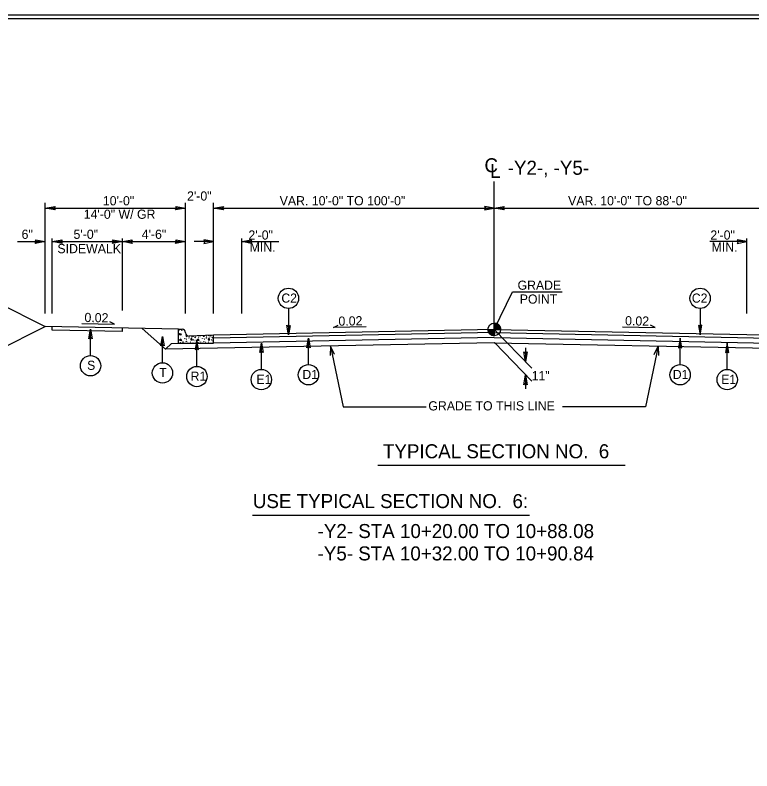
# Model space of a CAD drawing. Extents: x 1901670 to 1902225, y 193498 to 194278.
# Drawn here: x 1902005.8 to 1902058.3, y 193881.9 to 193935.8 of the extents above; entities that cross this region are included whole.
import ezdxf

# ---------------------------------------------------------------- set-up
doc = ezdxf.new("R2010")
doc.units = 0
for name, color, linetype in [('Old_Level_1', 7, 'Continuous'), ('Old_Level_11', 7, 'Continuous'), ('Old_Level_2', 7, 'Continuous'), ('Old_Level_20', 7, 'Continuous'), ('Prop Dimension', 7, 'Continuous'), ('Sheet Border Standard 30in CELL', 7, 'Continuous'), ('Sheet Plot Border Inside CELL', 7, 'Continuous'), ('Typical Curb CELL', 7, 'Continuous'), ('Typical Pavement Slope CELL', 7, 'Continuous'), ('Typical Terminator CELL', 7, 'Continuous'), ('Typical Text Grade Point CELL', 7, 'Continuous')]:
    doc.layers.add(name, color=color, linetype=linetype)

# ---------------------------------------------------------------- blocks, each defined once
blk = doc.blocks.new('TERMINATOR')
at = {"layer": 'Typical Terminator CELL'}
blk.add_lwpolyline([(-0.469, 0.081), (0, 0), (-0.471, -0.083), (-0.411, 0)], close=True, dxfattribs=at)

msp = doc.modelspace()

# ---------------------------------------------------------------- linework, layer by layer
at = {"layer": 'Old_Level_1'}
for p, q in [((1902039.897, 193913.36), (1902039.897, 193923.919)), ((1902010.511, 193913.786), (1902012.826, 193913.738)), ((1902012.826, 193913.738), (1902012.493, 193913.905)), ((1902039.897, 193913.36), (1902039.897, 193913.81)), ((1902014.816, 193913.429), (1902016.474, 193911.944)), ((1902039.897, 193913.36), (1902019.897, 193912.96)), ((1902028.443, 193913.503), (1902028.776, 193913.67)), ((1902030.758, 193913.551), (1902028.443, 193913.503)), ((1902039.447, 193913.36), (1902039.897, 193913.36)), ((1902039.896, 193912.91), (1902039.897, 193913.36)), ((1902039.897, 193913.36), (1902039.896, 193912.91)), ((1902039.897, 193913.36), (1902042.569, 193910.6)), ((1902040.347, 193913.36), (1902039.897, 193913.36)), ((1902039.897, 193913.36), (1902057.897, 193913)), ((1902049.035, 193913.551), (1902051.35, 193913.503)), ((1902051.35, 193913.503), (1902051.017, 193913.67)), ((1902039.897, 193913.142), (1902019.897, 193912.742)), ((1902039.897, 193912.777), (1902019.897, 193912.377)), ((1902039.897, 193913.142), (1902059.897, 193912.742)), ((1902039.897, 193912.777), (1902059.897, 193912.377)), ((1902057.897, 193913), (1902059.897, 193912.96)), ((1902039.897, 193912.413), (1902016.474, 193911.944)), ((1902016.897, 193912.367), (1902016.474, 193911.944)), ((1902016.897, 193912.367), (1902017.397, 193912.377)), ((1902039.897, 193912.413), (1902063.319, 193911.944)), ((1902039.899, 193912.426), (1902042.569, 193909.667)), ((1902042.123, 193912.06), (1902042.123, 193911.06)), ((1902042.125, 193910.125), (1902042.125, 193909.125))]:
    msp.add_line(p, q, dxfattribs=at)
for points in [[(1902039.901, 193913.81), (1902039.901, 193913.81), (1902039.901, 193913.36)], [(1902039.91, 193913.81), (1902039.91, 193913.36)], [(1902039.919, 193913.809), (1902039.919, 193913.36)], [(1902039.928, 193913.809), (1902039.928, 193913.36)], [(1902039.937, 193913.808), (1902039.937, 193913.36)], [(1902039.946, 193913.807), (1902039.946, 193913.36)], [(1902039.955, 193913.806), (1902039.955, 193913.36)], [(1902039.964, 193913.805), (1902039.964, 193913.36)], [(1902039.973, 193913.804), (1902039.973, 193913.36)], [(1902039.982, 193913.802), (1902039.982, 193913.36)], [(1902039.991, 193913.8), (1902039.991, 193913.36)], [(1902040, 193913.798), (1902040, 193913.36)], [(1902040.009, 193913.796), (1902040.009, 193913.36)], [(1902040.018, 193913.793), (1902040.018, 193913.36)], [(1902040.027, 193913.791), (1902040.027, 193913.36)], [(1902040.036, 193913.788), (1902040.036, 193913.36)], [(1902040.045, 193913.785), (1902040.045, 193913.36)], [(1902040.054, 193913.782), (1902040.054, 193913.36)], [(1902040.063, 193913.778), (1902040.063, 193913.36)], [(1902040.072, 193913.774), (1902040.072, 193913.36)], [(1902040.081, 193913.77), (1902040.081, 193913.36)], [(1902040.09, 193913.766), (1902040.09, 193913.36)], [(1902040.099, 193913.762), (1902040.099, 193913.36)], [(1902040.108, 193913.757), (1902040.108, 193913.36)], [(1902040.117, 193913.752), (1902040.117, 193913.36)], [(1902040.126, 193913.747), (1902040.126, 193913.36)], [(1902039.449, 193913.36), (1902039.449, 193913.311)], [(1902039.458, 193913.36), (1902039.458, 193913.258)], [(1902039.467, 193913.36), (1902039.467, 193913.226)], [(1902039.476, 193913.36), (1902039.476, 193913.199)], [(1902039.485, 193913.36), (1902039.485, 193913.178)], [(1902039.494, 193913.36), (1902039.494, 193913.159)], [(1902039.503, 193913.36), (1902039.503, 193913.142)], [(1902039.512, 193913.36), (1902039.512, 193913.126)], [(1902039.521, 193913.36), (1902039.521, 193913.112)], [(1902039.53, 193913.36), (1902039.53, 193913.099)], [(1902039.539, 193913.36), (1902039.539, 193913.087)], [(1902039.548, 193913.36), (1902039.548, 193913.076)], [(1902039.557, 193913.36), (1902039.557, 193913.065)], [(1902039.566, 193913.36), (1902039.566, 193913.055)], [(1902039.575, 193913.36), (1902039.575, 193913.045)], [(1902039.584, 193913.36), (1902039.584, 193913.036)], [(1902039.593, 193913.36), (1902039.593, 193913.028)], [(1902039.602, 193913.36), (1902039.602, 193913.02)], [(1902039.611, 193913.36), (1902039.611, 193913.012)], [(1902039.62, 193913.36), (1902039.62, 193913.005)], [(1902039.629, 193913.36), (1902039.629, 193912.998)], [(1902039.638, 193913.36), (1902039.638, 193912.992)], [(1902039.647, 193913.36), (1902039.647, 193912.986)], [(1902039.656, 193913.36), (1902039.656, 193912.98)], [(1902039.665, 193913.36), (1902039.665, 193912.974)], [(1902039.674, 193913.36), (1902039.674, 193912.969)], [(1902039.683, 193913.36), (1902039.683, 193912.964)], [(1902039.692, 193913.36), (1902039.692, 193912.959)], [(1902039.701, 193913.36), (1902039.701, 193912.955)], [(1902039.71, 193913.36), (1902039.71, 193912.951)], [(1902039.719, 193913.36), (1902039.719, 193912.947)], [(1902039.728, 193913.36), (1902039.728, 193912.943)], [(1902039.737, 193913.36), (1902039.737, 193912.939)], [(1902039.746, 193913.36), (1902039.746, 193912.936)], [(1902039.755, 193913.36), (1902039.755, 193912.933)], [(1902039.764, 193913.36), (1902039.764, 193912.93)], [(1902039.773, 193913.36), (1902039.773, 193912.928)], [(1902039.782, 193913.36), (1902039.782, 193912.925)], [(1902039.791, 193913.36), (1902039.791, 193912.923)], [(1902039.8, 193913.36), (1902039.8, 193912.921)], [(1902039.809, 193913.36), (1902039.809, 193912.919)], [(1902039.818, 193913.36), (1902039.818, 193912.917)], [(1902039.827, 193913.36), (1902039.827, 193912.916)], [(1902039.836, 193913.36), (1902039.836, 193912.914)], [(1902039.845, 193913.36), (1902039.845, 193912.913)], [(1902039.854, 193913.36), (1902039.854, 193912.912)], [(1902039.863, 193913.36), (1902039.863, 193912.911)], [(1902039.872, 193913.36), (1902039.872, 193912.911)], [(1902039.881, 193913.36), (1902039.881, 193912.91)], [(1902039.89, 193913.36), (1902039.89, 193912.91), (1902039.89, 193912.91)], [(1902040.135, 193913.742), (1902040.135, 193913.36)], [(1902040.144, 193913.736), (1902040.144, 193913.36)], [(1902040.153, 193913.73), (1902040.153, 193913.36)], [(1902040.162, 193913.723), (1902040.162, 193913.36)], [(1902040.171, 193913.717), (1902040.171, 193913.36)], [(1902040.18, 193913.71), (1902040.18, 193913.36)], [(1902040.189, 193913.702), (1902040.189, 193913.36)], [(1902040.198, 193913.694), (1902040.198, 193913.36)], [(1902040.207, 193913.686), (1902040.207, 193913.36)], [(1902040.216, 193913.677), (1902040.216, 193913.36)], [(1902040.225, 193913.668), (1902040.225, 193913.36)], [(1902040.234, 193913.658), (1902040.234, 193913.36)], [(1902040.243, 193913.647), (1902040.243, 193913.36)], [(1902040.252, 193913.636), (1902040.252, 193913.36)], [(1902040.261, 193913.624), (1902040.261, 193913.36)], [(1902040.27, 193913.611), (1902040.27, 193913.36)], [(1902040.279, 193913.597), (1902040.279, 193913.36)], [(1902040.288, 193913.582), (1902040.288, 193913.36)], [(1902040.297, 193913.566), (1902040.297, 193913.36)], [(1902040.306, 193913.547), (1902040.306, 193913.36)], [(1902040.315, 193913.526), (1902040.315, 193913.36)], [(1902040.324, 193913.501), (1902040.324, 193913.36)], [(1902040.333, 193913.47), (1902040.333, 193913.36)], [(1902040.342, 193913.424), (1902040.342, 193913.36)], [(1902028.512, 193911.57), (1902028.219, 193912.179), (1902028.191, 193911.504)], [(1902028.219, 193912.179), (1902029.128, 193907.833)], [(1902051.575, 193912.179), (1902050.665, 193907.833)], [(1902051.281, 193911.57), (1902051.575, 193912.179), (1902051.602, 193911.504)], [(1902029.128, 193907.833), (1902035.043, 193907.833)], [(1902050.665, 193907.833), (1902044.75, 193907.833)]]:
    msp.add_lwpolyline(points, dxfattribs=at)
msp.add_circle((1902039.896, 193913.36), 0.45, dxfattribs=at)
for start, end in [(359.9905, 89.9905), (179.9905, 269.9905)]:
    msp.add_arc((1902039.896, 193913.36), 0.45, start, end, dxfattribs=at)
at = {"layer": 'Old_Level_11'}
for p, q in [((1902025.231, 193914.854), (1902025.231, 193912.98)), ((1902054.562, 193914.854), (1902054.562, 193912.98)), ((1902011.127, 193911.5), (1902011.127, 193913.374)), ((1902016.251, 193910.984), (1902016.251, 193912.859)), ((1902026.656, 193910.858), (1902026.656, 193912.732)), ((1902053.138, 193910.858), (1902053.138, 193912.732)), ((1902018.705, 193910.731), (1902018.705, 193912.605)), ((1902023.297, 193910.509), (1902023.297, 193912.384)), ((1902056.497, 193910.509), (1902056.497, 193912.384)), ((1902031.604, 193903.683), (1902048.23, 193903.683)), ((1902032.604, 193903.683), (1902049.23, 193903.683)), ((1902022.666, 193900.132), (1902042.41, 193900.132))]:
    msp.add_line(p, q, dxfattribs=at)
for points in [[(1902011.012, 193912.703), (1902011.127, 193913.374), (1902011.247, 193912.699), (1902011.127, 193912.785)], [(1902025.347, 193913.651), (1902025.231, 193912.98), (1902025.112, 193913.655), (1902025.231, 193913.569)], [(1902054.447, 193913.651), (1902054.562, 193912.98), (1902054.682, 193913.655), (1902054.562, 193913.569)], [(1902016.135, 193912.187), (1902016.251, 193912.859), (1902016.37, 193912.183), (1902016.251, 193912.269)], [(1902026.54, 193912.061), (1902026.656, 193912.732), (1902026.775, 193912.057), (1902026.656, 193912.143)], [(1902053.253, 193912.061), (1902053.138, 193912.732), (1902053.018, 193912.057), (1902053.138, 193912.143)], [(1902018.821, 193911.934), (1902018.705, 193912.605), (1902018.586, 193911.93), (1902018.705, 193912.016)], [(1902023.181, 193911.712), (1902023.297, 193912.384), (1902023.416, 193911.708), (1902023.297, 193911.794)], [(1902056.612, 193911.712), (1902056.497, 193912.384), (1902056.377, 193911.708), (1902056.497, 193911.794)]]:
    msp.add_lwpolyline(points, close=True, dxfattribs=at)
for centre in [(1902025.231, 193915.579), (1902054.562, 193915.579), (1902011.127, 193910.775), (1902016.251, 193910.259), (1902018.705, 193910.006), (1902026.656, 193910.133), (1902053.137, 193910.133), (1902023.297, 193909.784), (1902056.497, 193909.784)]:
    msp.add_circle(centre, 0.725, dxfattribs=at)
at = {"layer": 'Prop Dimension'}
for p, q in [((1902007.897, 193914.498), (1902007.897, 193922.38)), ((1902017.897, 193914.498), (1902017.897, 193922.38)), ((1902019.897, 193914.498), (1902019.897, 193922.38)), ((1902007.897, 193922.01), (1902017.897, 193922.01)), ((1902019.897, 193922.01), (1902039.897, 193922.01)), ((1902039.897, 193922.01), (1902059.897, 193922.01)), ((1902008.397, 193914.498), (1902008.397, 193919.848)), ((1902013.397, 193914.719), (1902013.397, 193919.848)), ((1902021.897, 193914.498), (1902021.897, 193919.848)), ((1902057.897, 193914.498), (1902057.897, 193919.848)), ((1902005.931, 193919.621), (1902007.897, 193919.621)), ((1902008.397, 193919.621), (1902013.397, 193919.621)), ((1902013.397, 193919.621), (1902017.897, 193919.621)), ((1902019.897, 193919.621), (1902018.513, 193919.621)), ((1902021.897, 193919.621), (1902024.542, 193919.621)), ((1902057.897, 193919.621), (1902055.251, 193919.621))]:
    msp.add_line(p, q, dxfattribs=at)
at = {"layer": 'Sheet Border Standard 30in CELL'}
msp.add_lwpolyline([(1902132.544, 193935.514), (1901982.544, 193935.514), (1901982.544, 193830.514), (1902132.544, 193830.514)], close=True, dxfattribs=at)
at = {"layer": 'Sheet Plot Border Inside CELL'}
msp.add_lwpolyline([(1902133.794, 193935.769), (1901967.144, 193935.769), (1901967.144, 193830.259), (1902133.794, 193830.259)], close=True, dxfattribs=at)
at = {"layer": 'Typical Curb CELL'}
for p, q in [((1902017.397, 193912.377), (1902017.397, 193913.377)), ((1902017.397, 193913.377), (1902017.657, 193913.377)), ((1902017.433, 193912.999), (1902017.588, 193913.044)), ((1902017.571, 193912.953), (1902017.433, 193912.999)), ((1902017.559, 193912.68), (1902017.456, 193912.605)), ((1902017.622, 193912.566), (1902017.559, 193912.68)), ((1902017.588, 193913.044), (1902017.571, 193912.953)), ((1902017.897, 193913.127), (1902017.897, 193913.137)), ((1902019.897, 193912.96), (1902018.146, 193912.887)), ((1902018.301, 193912.736), (1902018.267, 193912.623)), ((1902018.386, 193912.617), (1902018.301, 193912.736)), ((1902018.808, 193912.68), (1902018.705, 193912.605)), ((1902018.871, 193912.566), (1902018.808, 193912.68)), ((1902019.55, 193912.736), (1902019.515, 193912.623)), ((1902019.636, 193912.617), (1902019.55, 193912.736)), ((1902019.897, 193912.377), (1902019.897, 193912.96)), ((1902017.397, 193912.377), (1902019.897, 193912.377)), ((1902017.456, 193912.605), (1902017.622, 193912.566)), ((1902018.267, 193912.623), (1902018.386, 193912.617)), ((1902018.705, 193912.605), (1902018.871, 193912.566)), ((1902019.515, 193912.623), (1902019.636, 193912.617))]:
    msp.add_line(p, q, dxfattribs=at)
for centre in [(1902017.41, 193913.267), (1902017.627, 193913.301), (1902017.462, 193913.084), (1902017.559, 193912.811), (1902017.679, 193912.862), (1902017.856, 193912.697), (1902017.936, 193912.89), (1902017.953, 193912.84), (1902017.981, 193912.668), (1902018.13, 193912.754), (1902018.158, 193912.856), (1902018.352, 193912.817), (1902018.449, 193912.871), (1902018.558, 193912.777), (1902018.614, 193912.811), (1902018.631, 193912.714), (1902018.808, 193912.811), (1902018.928, 193912.862), (1902019.105, 193912.697), (1902019.185, 193912.89), (1902019.202, 193912.84), (1902019.23, 193912.668), (1902019.379, 193912.754), (1902019.407, 193912.856), (1902019.556, 193912.919), (1902019.601, 193912.817), (1902019.698, 193912.902), (1902019.807, 193912.777), (1902019.863, 193912.811), (1902019.88, 193912.714), (1902017.542, 193912.423), (1902017.713, 193912.463), (1902017.89, 193912.4), (1902017.947, 193912.514), (1902018.061, 193912.429), (1902018.267, 193912.452), (1902018.426, 193912.383), (1902018.478, 193912.617), (1902018.574, 193912.571), (1902018.637, 193912.406), (1902018.791, 193912.423), (1902018.962, 193912.463), (1902019.139, 193912.4), (1902019.196, 193912.514), (1902019.31, 193912.429), (1902019.516, 193912.452), (1902019.676, 193912.383), (1902019.727, 193912.617), (1902019.823, 193912.571), (1902019.886, 193912.406)]:
    msp.add_circle(centre, 0.00802, dxfattribs=at)
for centre, start, end in [((1902017.657, 193913.137), 0.0002, 90.0002), ((1902018.136, 193913.127), 180.0002, 272.3846)]:
    msp.add_arc(centre, 0.24, start, end, dxfattribs=at)
at = {"layer": 'Typical Pavement Slope CELL'}
for p, q in [((1901999.94, 193917.545), (1902007.897, 193913.567)), ((1901999.94, 193909.588), (1902007.897, 193913.567)), ((1902017.397, 193913.377), (1902007.897, 193913.567)), ((1902008.397, 193913.307), (1902008.397, 193913.557)), ((1902013.397, 193913.207), (1902008.397, 193913.307)), ((1902013.397, 193913.207), (1902013.397, 193913.457))]:
    msp.add_line(p, q, dxfattribs=at)
at = {"layer": 'Typical Text Grade Point CELL'}
for p, q in [((1902039.897, 193913.36), (1902041.192, 193916.033)), ((1902041.192, 193916.033), (1902044.73, 193916.033))]:
    msp.add_line(p, q, dxfattribs=at)

# ---------------------------------------------------------------- block references
at = {"layer": 'Old_Level_1', "xscale": 1.5, "yscale": 1.5}
for p, rotation in [((1902042.123, 193911.06), -90), ((1902042.125, 193910.125), 90)]:
    msp.add_blockref('TERMINATOR', p, dxfattribs=dict(at, rotation=rotation))
at = {"layer": 'Prop Dimension', "xscale": 1.5, "yscale": 1.5, "rotation": 180}
for p in [(1902007.897, 193922.01), (1902019.897, 193922.01), (1902039.897, 193922.01), (1902008.397, 193919.621), (1902013.397, 193919.621), (1902021.897, 193919.621)]:
    msp.add_blockref('TERMINATOR', p, dxfattribs=at)
at = {"layer": 'Prop Dimension', "xscale": 1.5}
for p, yscale in [((1902017.897, 193922.01), 1.5), ((1902039.897, 193922.01), -1.5), ((1902007.897, 193919.621), 1.5), ((1902013.397, 193919.621), 1.5), ((1902017.897, 193919.621), 1.5), ((1902019.897, 193919.621), -1.5), ((1902057.897, 193919.621), -1.5)]:
    msp.add_blockref('TERMINATOR', p, dxfattribs=dict(at, yscale=yscale))

# ---------------------------------------------------------------- texts
at = {"layer": 'Old_Level_1'}
for s, height, p in [('11"', 0.6491, (1902042.564, 193909.744)), ('GRADE TO THIS LINE', 0.656, (1902035.195, 193907.587))]:
    msp.add_text(s, height=height, dxfattribs=at).set_placement(p)
at = {"layer": 'Old_Level_11'}
for s, p in [('TYPICAL SECTION NO.  6', (1902031.96, 193904.177)), ('USE TYPICAL SECTION NO.  6:', (1902022.691, 193900.626)), ('-Y2- STA 10+20.00 TO 10+88.08', (1902027.306, 193898.49)), ('-Y5- STA 10+32.00 TO 10+90.84', (1902027.302, 193896.894))]:
    msp.add_text(s, height=1, dxfattribs=at).set_placement(p)
at = {"layer": 'Old_Level_2'}
msp.add_text('C', height=1, dxfattribs=at).set_placement((1902039.195, 193924.565))
for s, height, rotation, p in [('L', 1, 359.9469, (1902039.597, 193924.161)), ('-Y2-, -Y5-', 1, 359.9469, (1902040.852, 193924.39)), ('0.02', 0.656, 358.8084, (1902010.688, 193913.893)), ('0.02', 0.656, 1.1916, (1902028.798, 193913.622)), ('0.02', 0.656, 358.8084, (1902049.212, 193913.659))]:
    msp.add_text(s, height=height, rotation=rotation, dxfattribs=at).set_placement(p)
at = {"layer": 'Old_Level_20'}
for s, height, p in [('C2', 0.6491, (1902024.725, 193915.273)), ('C2', 0.6491, (1902053.973, 193915.273)), ('S', 0.649, (1902010.884, 193910.482)), ('T', 0.649, (1902016.023, 193909.966)), ('R1', 0.6491, (1902018.26, 193909.702)), ('E1', 0.6491, (1902022.951, 193909.481)), ('D1', 0.6491, (1902026.222, 193909.829)), ('D1', 0.6491, (1902052.616, 193909.829)), ('E1', 0.6491, (1902056.063, 193909.481))]:
    msp.add_text(s, height=height, dxfattribs=at).set_placement(p)
at = {"layer": 'Prop Dimension'}
for s, p in [('2\'-0" ', (1902018.005, 193922.549)), ('10\'-0" ', (1902012.003, 193922.208)), ('VAR. 10\'-0" TO 100\'-0"', (1902024.602, 193922.208)), ('VAR. 10\'-0" TO 88\'-0"', (1902045.155, 193922.208)), ('14\'-0" W/ GR ', (1902010.641, 193921.248)), ('6" ', (1902006.213, 193919.819)), ('5\'-0" ', (1902009.915, 193919.819)), ('4\'-6" ', (1902014.774, 193919.819)), ('2\'-0"', (1902022.376, 193919.766)), ('2\'-0"', (1902055.293, 193919.766)), ('SIDEWALK', (1902008.764, 193918.797)), ('MIN. ', (1902022.461, 193918.906)), ('MIN. ', (1902055.378, 193918.906))]:
    msp.add_text(s, height=0.656, dxfattribs=at).set_placement(p)
at = {"layer": 'Typical Text Grade Point CELL'}
for s, p in [('GRADE', (1902041.556, 193916.19)), ('POINT', (1902041.713, 193915.201))]:
    msp.add_text(s, height=0.6525, dxfattribs=at).set_placement(p)

doc.saveas('drawing.dxf')
